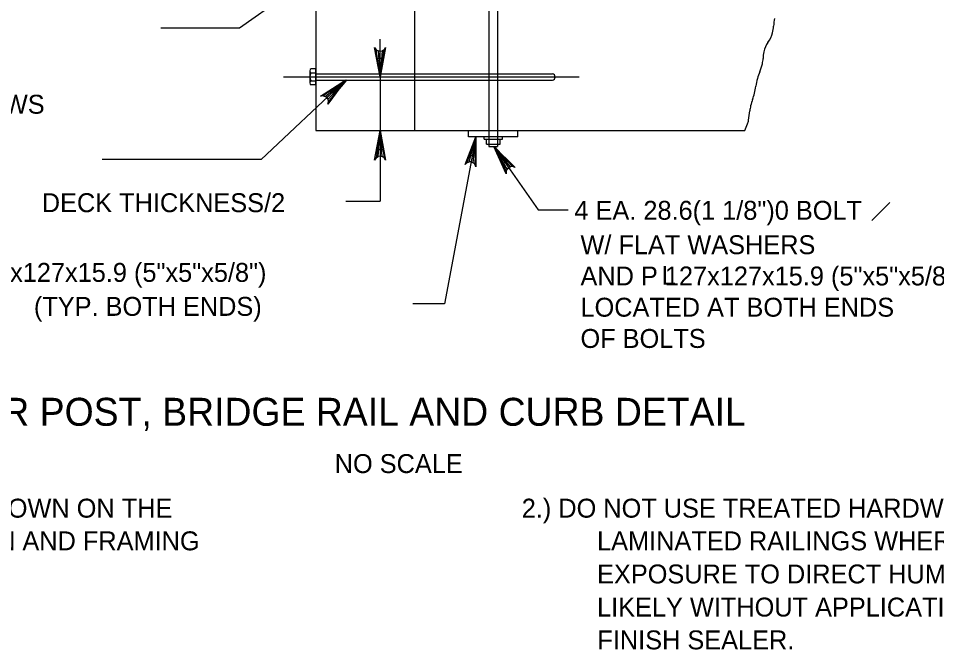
# Model space of a CAD drawing. Extents: x 0 to 36.3, y -66 to 0.
# Drawn here: x 5.26 to 11.08, y -9.31 to -5.3 of the extents above; entities that cross this region are included whole.
import ezdxf

# ---------------------------------------------------------------- set-up
doc = ezdxf.new("R2010")
doc.units = 0
for name, color, linetype in [('2', 7, 'Continuous'), ('3', 7, 'Continuous'), ('4', 7, 'Continuous')]:
    doc.layers.add(name, color=color, linetype=linetype)

msp = doc.modelspace()

# ---------------------------------------------------------------- linework, layer by layer
at = {"layer": '2'}
for p, q in [((7.7728, -3.0782), (7.7728, -6.0157)), ((7.1478, -3.1407), (7.1478, -6.0157)), ((8.2453, -4.4141), (8.2453, -6.1172)), ((8.3001, -4.4141), (8.3001, -6.1172)), ((7.1098, -5.6362), (7.1098, -5.7132)), ((7.1102, -5.6397), (7.1102, -5.6397)), ((7.1102, -5.6411), (7.1102, -5.6411)), ((7.1102, -5.6425), (7.1102, -5.6425)), ((7.1102, -5.6439), (7.1102, -5.6439)), ((7.1102, -5.6453), (7.1102, -5.6453)), ((7.1117, -5.6432), (7.1117, -5.6432)), ((7.1117, -5.6447), (7.1117, -5.6447)), ((7.1117, -5.6461), (7.1117, -5.6461)), ((7.1131, -5.6453), (7.1131, -5.6453)), ((7.1478, -5.6244), (7.1188, -5.6244)), ((7.1478, -5.7259), (7.1478, -5.6244)), ((6.9436, -5.6752), (8.817, -5.6752)), ((7.1102, -5.6467), (7.1102, -5.6467)), ((7.1102, -5.6482), (7.1102, -5.6482)), ((7.1102, -5.6498), (7.1102, -5.6498)), ((7.1102, -5.6512), (7.1102, -5.6512)), ((7.1102, -5.6526), (7.1102, -5.6526)), ((7.1102, -5.654), (7.1102, -5.654)), ((7.1102, -5.6554), (7.1102, -5.6554)), ((7.1102, -5.6568), (7.1102, -5.6568)), ((7.1102, -5.6582), (7.1102, -5.6582)), ((7.1102, -5.6596), (7.1102, -5.6596)), ((7.1102, -5.661), (7.1102, -5.661)), ((7.1102, -5.6624), (7.1102, -5.6624)), ((7.1102, -5.6638), (7.1102, -5.6638)), ((7.1102, -5.6652), (7.1102, -5.6652)), ((7.1102, -5.6667), (7.1102, -5.6667)), ((7.1102, -5.6681), (7.1102, -5.6681)), ((7.1102, -5.6807), (7.1102, -5.6807)), ((7.1102, -5.6821), (7.1102, -5.6821)), ((7.1102, -5.6835), (7.1102, -5.6835)), ((7.1102, -5.6849), (7.1102, -5.6849)), ((7.1102, -5.6863), (7.1102, -5.6863)), ((7.1102, -5.6877), (7.1102, -5.6877)), ((7.1102, -5.6892), (7.1102, -5.6892)), ((7.1102, -5.6906), (7.1102, -5.6906)), ((7.1102, -5.692), (7.1102, -5.692)), ((7.1102, -5.6933), (7.1102, -5.6933)), ((7.1102, -5.6947), (7.1102, -5.6947)), ((7.1102, -5.6962), (7.1102, -5.6962)), ((7.1102, -5.6976), (7.1102, -5.6976)), ((7.1102, -5.699), (7.1102, -5.699)), ((7.1102, -5.7004), (7.1102, -5.7004)), ((7.1102, -5.7018), (7.1102, -5.7018)), ((7.1102, -5.7032), (7.1102, -5.7032)), ((7.1117, -5.6474), (7.1117, -5.6474)), ((7.1117, -5.6488), (7.1117, -5.6488)), ((7.1117, -5.6491), (7.1117, -5.6491)), ((7.1117, -5.6505), (7.1117, -5.6505)), ((7.1117, -5.6518), (7.1117, -5.6518)), ((7.1117, -5.6533), (7.1117, -5.6533)), ((7.1117, -5.6547), (7.1117, -5.6547)), ((7.1117, -5.6562), (7.1117, -5.6562)), ((7.1117, -5.6575), (7.1117, -5.6575)), ((7.1117, -5.6589), (7.1117, -5.6589)), ((7.1117, -5.6603), (7.1117, -5.6603)), ((7.1117, -5.6617), (7.1117, -5.6617)), ((7.1117, -5.6871), (7.1117, -5.6871)), ((7.1117, -5.6885), (7.1117, -5.6885)), ((7.1117, -5.6899), (7.1117, -5.6899)), ((7.1117, -5.6913), (7.1117, -5.6913)), ((7.1117, -5.6927), (7.1117, -5.6927)), ((7.1117, -5.6941), (7.1117, -5.6941)), ((7.1117, -5.6955), (7.1117, -5.6955)), ((7.1117, -5.6968), (7.1117, -5.6968)), ((7.1117, -5.6983), (7.1117, -5.6983)), ((7.1117, -5.6997), (7.1117, -5.6997)), ((7.1117, -5.7012), (7.1117, -5.7012)), ((7.1117, -5.7025), (7.1117, -5.7025)), ((7.1117, -5.7039), (7.1117, -5.7039)), ((7.1131, -5.6467), (7.1131, -5.6467)), ((7.1131, -5.6482), (7.1131, -5.6482)), ((7.1131, -5.6498), (7.1131, -5.6498)), ((7.1131, -5.6512), (7.1131, -5.6512)), ((7.1131, -5.6526), (7.1131, -5.6526)), ((7.1131, -5.654), (7.1131, -5.654)), ((7.1131, -5.6554), (7.1131, -5.6554)), ((7.1131, -5.6568), (7.1131, -5.6568)), ((7.1131, -5.6582), (7.1131, -5.6582)), ((7.1131, -5.6906), (7.1131, -5.6906)), ((7.1131, -5.692), (7.1131, -5.692)), ((7.1131, -5.6933), (7.1131, -5.6933)), ((7.1131, -5.6947), (7.1131, -5.6947)), ((7.1131, -5.6962), (7.1131, -5.6962)), ((7.1131, -5.6976), (7.1131, -5.6976)), ((7.1131, -5.699), (7.1131, -5.699)), ((7.1131, -5.7004), (7.1131, -5.7004)), ((7.1131, -5.7018), (7.1131, -5.7018)), ((7.1131, -5.7032), (7.1131, -5.7032)), ((7.1145, -5.6475), (7.1145, -5.6475)), ((7.1145, -5.6488), (7.1145, -5.6488)), ((7.1145, -5.6491), (7.1145, -5.6491)), ((7.1145, -5.6505), (7.1145, -5.6505)), ((7.1145, -5.6518), (7.1145, -5.6518)), ((7.1145, -5.6533), (7.1145, -5.6533)), ((7.1145, -5.6547), (7.1145, -5.6547)), ((7.1145, -5.6941), (7.1145, -5.6941)), ((7.1145, -5.6955), (7.1145, -5.6955)), ((7.1145, -5.6968), (7.1145, -5.6968)), ((7.1145, -5.6983), (7.1145, -5.6983)), ((7.1145, -5.6997), (7.1145, -5.6997)), ((7.1145, -5.7011), (7.1145, -5.7011)), ((7.1158, -5.6482), (7.1158, -5.6482)), ((7.1158, -5.6498), (7.1158, -5.6498)), ((7.1158, -5.6512), (7.1158, -5.6512)), ((7.1158, -5.6526), (7.1158, -5.6526)), ((7.1158, -5.6962), (7.1158, -5.6962)), ((7.1158, -5.6976), (7.1158, -5.6976)), ((7.1158, -5.699), (7.1158, -5.699)), ((7.1158, -5.7004), (7.1158, -5.7004)), ((7.1172, -5.6488), (7.1172, -5.6488)), ((7.1172, -5.6491), (7.1172, -5.6491)), ((7.1172, -5.6505), (7.1172, -5.6505)), ((7.1172, -5.6983), (7.1172, -5.6983)), ((7.1172, -5.6997), (7.1172, -5.6997)), ((7.1188, -5.6489), (7.1478, -5.6489)), ((7.1188, -5.6997), (7.1478, -5.6997)), ((7.1478, -5.6562), (8.6478, -5.6562)), ((7.1478, -5.6952), (8.6478, -5.6952)), ((7.1102, -5.7046), (7.1102, -5.7046)), ((7.1102, -5.706), (7.1102, -5.706)), ((7.1102, -5.7074), (7.1102, -5.7074)), ((7.1102, -5.7088), (7.1102, -5.7088)), ((7.1117, -5.7053), (7.1117, -5.7053)), ((7.1478, -5.7259), (7.1188, -5.7259)), ((7.1478, -6.0157), (9.8673, -6.0157)), ((8.1165, -6.0547), (8.1165, -6.0157)), ((8.429, -6.0547), (8.429, -6.0157)), ((8.429, -6.0547), (8.1165, -6.0547)), ((8.2141, -6.0703), (8.2141, -6.0547)), ((8.2141, -6.0703), (8.3313, -6.0703)), ((8.2297, -6.1016), (8.2297, -6.0703)), ((8.2297, -6.1016), (8.3157, -6.1016)), ((8.3157, -6.1016), (8.3157, -6.0703)), ((8.3313, -6.0703), (8.3313, -6.0547)), ((8.2453, -6.1172), (8.3001, -6.1172))]:
    msp.add_line(p, q, dxfattribs=at)
for centre, radius, start, end in [((9.8171, -5.3394), 0.233, 346.27514, 356.42716), ((10.3993, -5.3757), 0.3504, 168.15221, 176.42716), ((9.8754, -5.3537), 0.1729, 323.40858, 346.27514), ((10.1361, -5.5472), 0.1517, 143.40858, 167.83875), ((10.1907, -5.5589), 0.2076, 167.83875, 179.70998), ((9.8411, -5.5572), 0.142, 345.34306, 359.70998), ((7.1226, -5.6366), 0.0128, 107.45181, 252.54819), ((10.2104, -5.7496), 0.271, 156.60185, 166.38398), ((9.6502, -5.5072), 0.3393, 336.60186, 345.34306), ((7.1502, -5.6743), 0.0404, 141.05, 218.95), ((7.1239, -5.7128), 0.0141, 111.28694, 178.17294), ((8.6451, -5.6757), 0.0197, 277.85987, 82.14013), ((10.5175, -5.824), 0.587, 166.38398, 171.19227), ((7.1239, -5.7128), 0.0141, 178.17294, 248.71305), ((9.4466, -5.6581), 0.4967, 345.96444, 351.19227), ((10.3494, -5.9711), 0.4592, 160.48289, 165.77345), ((9.5134, -5.6748), 0.4278, 340.48289, 345.96444), ((10.0973, -5.9072), 0.1991, 165.77345, 175.29217), ((9.2711, -5.8391), 0.6299, 349.9453, 355.29217), ((9.3948, -5.795), 0.5214, 334.95891, 340.08642), ((9.7522, -5.9244), 0.1413, 340.08642, 349.9453)]:
    msp.add_arc(centre, radius, start, end, dxfattribs=at)
at = {"layer": '3'}
for p, q in [((7.0462, -5.0949), (6.6647, -5.3667)), ((6.6647, -5.3667), (6.1648, -5.3667)), ((7.5558, -5.5552), (7.5558, -5.4352)), ((7.3367, -5.6952), (6.8007, -6.1985)), ((7.5558, -5.6752), (7.5558, -6.4637)), ((8.1627, -6.0547), (7.9627, -7.1127)), ((7.5558, -6.1357), (7.5558, -6.2557)), ((8.2765, -6.1172), (8.5565, -6.5179)), ((6.8007, -6.1985), (5.7935, -6.1985)), ((7.3374, -6.4637), (7.5558, -6.4637)), ((8.5565, -6.5179), (8.7472, -6.5179)), ((10.6722, -6.5847), (10.7865, -6.4704)), ((7.9627, -7.1127), (7.7628, -7.1127))]:
    msp.add_line(p, q, dxfattribs=at)
for points in [[(7.5558, -5.6752), (7.5209, -5.4887), (7.5308, -5.5031), (7.5433, -5.5105), (7.5558, -5.5127), (7.5683, -5.5105), (7.5808, -5.5031), (7.5907, -5.4887), (7.5558, -5.6752), (7.5808, -5.5031), (7.5683, -5.5105), (7.5558, -5.6752), (7.5558, -5.5127), (7.5433, -5.5105), (7.5558, -5.6752), (7.5308, -5.5031)], [(7.3367, -5.6952), (7.2247, -5.8483), (7.2284, -5.8312), (7.2252, -5.8171), (7.2182, -5.8065), (7.2082, -5.7988), (7.1942, -5.7947), (7.1769, -5.7973), (7.3367, -5.6952), (7.1942, -5.7947), (7.2082, -5.7988), (7.3367, -5.6952), (7.2182, -5.8065), (7.2252, -5.8171), (7.3367, -5.6952), (7.2284, -5.8312)], [(7.5558, -6.0157), (7.5907, -6.2021), (7.5808, -6.1877), (7.5683, -6.1803), (7.5558, -6.1782), (7.5433, -6.1803), (7.5308, -6.1877), (7.5209, -6.2021), (7.5558, -6.0157), (7.5308, -6.1877), (7.5433, -6.1803), (7.5558, -6.0157), (7.5558, -6.1782), (7.5683, -6.1803), (7.5558, -6.0157), (7.5808, -6.1877)], [(8.1627, -6.0547), (8.1624, -6.2444), (8.1553, -6.2284), (8.1444, -6.2188), (8.1325, -6.2144), (8.1198, -6.2142), (8.1062, -6.2192), (8.0937, -6.2314), (8.1627, -6.0547), (8.1062, -6.2192), (8.1198, -6.2142), (8.1627, -6.0547), (8.1325, -6.2144), (8.1444, -6.2188), (8.1627, -6.0547), (8.1553, -6.2284)], [(8.2765, -6.1172), (8.4119, -6.25), (8.3956, -6.2439), (8.3811, -6.2451), (8.3696, -6.2504), (8.3606, -6.2593), (8.3546, -6.2726), (8.3547, -6.2901), (8.2765, -6.1172), (8.3546, -6.2726), (8.3606, -6.2593), (8.2765, -6.1172), (8.3696, -6.2504), (8.3811, -6.2451), (8.2765, -6.1172), (8.3956, -6.2439)]]:
    msp.add_lwpolyline(points, dxfattribs=at)
for points in [[(7.5358, -5.5552), (7.5758, -5.5552), (7.5558, -5.6752)], [(7.2402, -5.7584), (7.2663, -5.7887), (7.3442, -5.6952)], [(7.5358, -6.1357), (7.5758, -6.1357), (7.5558, -6.0157)], [(8.1207, -6.1689), (8.16, -6.1763), (8.1627, -6.0547)], [(8.3297, -6.2284), (8.3631, -6.2063), (8.2803, -6.1172)]]:
    msp.add_lwpolyline(points, close=True, dxfattribs=at)
at = {"layer": '4'}
for p, q in [((7.9088, -5.6752), (7.9088, -5.6752)), ((7.5558, -6.0157), (7.5558, -6.0157)), ((7.9088, -6.0157), (7.9088, -6.0157))]:
    msp.add_line(p, q, dxfattribs=at)

# ---------------------------------------------------------------- texts
at = {"layer": '2'}
msp.add_text('TIMBER POST, BRIDGE RAIL AND CURB DETAIL', height=0.177167, dxfattribs=at).set_placement((4.4365, -7.8868))
at = {"layer": '3'}
for s, p in [('2 EA. 31.8(1 1/4")0 X 610 (2\'-0")LAG SCREWS', (2.0647, -5.9084)), ('DECK THICKNESS/2', (5.4109, -6.5325)), ('4 EA. 28.6(1 1/8")0 BOLT', (8.7873, -6.5809)), ('W/ FLAT WASHERS', (8.8257, -6.799)), ('P 127x127x15.9 (5"x5"x5/8")', (4.7908, -6.9744)), ('AND P 127x127x15.9 (5"x5"x5/8")', (8.8257, -6.9971)), ('L', (9.3404, -6.9932)), ('(TYP. BOTH ENDS)', (5.3608, -7.1899)), ('LOCATED AT BOTH ENDS', (8.8257, -7.1952)), ('OF BOLTS', (8.8257, -7.3933)), ('NO SCALE', (7.2678, -8.1867)), ('1.) THIS PARAPET SHOWN ON THE', (3.537, -8.4693)), ('2.) DO NOT USE TREATED HARDWOOD GLUE', (8.4533, -8.4693)), ('GENERAL PLAN AND FRAMING', (4.0128, -8.6765)), ('LAMINATED RAILINGS WHERE PROLONGED', (8.9308, -8.6765)), ('EXPOSURE TO DIRECT HUMAN CONTACT IS', (8.9308, -8.8865)), ('LIKELY WITHOUT APPLICATION OF AN APPROVED', (8.9308, -9.0964)), ('FINISH SEALER.', (8.9328, -9.3045))]:
    msp.add_text(s, height=0.12, dxfattribs=at).set_placement(p)

doc.saveas('drawing.dxf')
